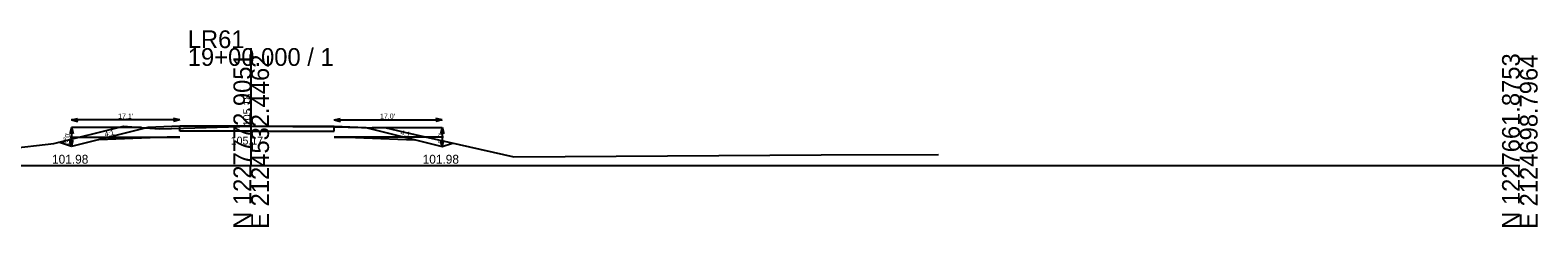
# Model space of a CAD drawing. Extents: x -26 to 1403, y -10 to 9574.
# Drawn here: x 1165.2 to 1402.8, y 8990.3 to 9021.3 of the extents above; entities that cross this region are included whole.
import ezdxf

# ---------------------------------------------------------------- set-up
doc = ezdxf.new("R2010")
doc.units = 0
for name, color, linetype in [('XS_CELL', 7, 'Continuous'), ('XS_P_FINISHED_GRADE', 7, 'Continuous'), ('XS_P_FINISHED_GRADE_ELEV_TX', 7, 'Continuous'), ('XS_P_SUBGRADE_GRANULAR', 7, 'Continuous'), ('XS_P_SUBGRADE_PAVEMENT', 7, 'Continuous'), ('XS_P_TX_CLEARZONE', 7, 'Continuous'), ('XS_P_TX_DCH', 7, 'Continuous'), ('XS_P_TX_FS_BS', 7, 'Continuous'), ('XS_X_GROUND', 7, 'Continuous'), ('XS_X_GROUND_TX', 7, 'Continuous')]:
    doc.layers.add(name, color=color, linetype=linetype)

msp = doc.modelspace()

# ---------------------------------------------------------------- linework, layer by layer
at = {"layer": 'XS_CELL'}
for p, q in [((1200, 9000), (1200, 9018.51)), ((1000, 9000), (1200, 9000)), ((1200, 9000), (1400, 9000))]:
    msp.add_line(p, q, dxfattribs=at)
at = {"layer": 'XS_P_FINISHED_GRADE'}
for p, q in [((1183.73, 9005.98), (1171.67, 9002.98)), ((1188.75, 9006.18), (1183.73, 9005.98)), ((1200, 9006.18), (1188.75, 9006.18)), ((1200, 9006.18), (1213.09, 9006.18)), ((1213.09, 9006.18), (1218.09, 9005.98)), ((1218.09, 9005.98), (1230.1, 9002.98)), ((1171.67, 9002.98), (1169.64, 9003.65)), ((1230.1, 9002.98), (1231.75, 9003.53))]:
    msp.add_line(p, q, dxfattribs=at)
at = {"layer": 'XS_P_SUBGRADE_GRANULAR'}
for p, q in [((1171.47, 9004.48), (1188.75, 9004.48)), ((1186.75, 9004.48), (1175.96, 9004.05)), ((1188.75, 9004.48), (1186.75, 9004.48)), ((1230.3, 9004.48), (1213.09, 9004.48)), ((1213.09, 9004.48), (1215.09, 9004.48)), ((1215.09, 9004.48), (1225.81, 9004.05))]:
    msp.add_line(p, q, dxfattribs=at)
at = {"layer": 'XS_P_SUBGRADE_PAVEMENT'}
for p, q in [((1188.75, 9005.43), (1188.75, 9006.18)), ((1213.09, 9005.43), (1213.09, 9006.18)), ((1200, 9005.43), (1188.75, 9005.43)), ((1200, 9005.43), (1213.09, 9005.43))]:
    msp.add_line(p, q, dxfattribs=at)
at = {"layer": 'XS_P_TX_CLEARZONE'}
for p, q in [((1171.67, 9005.98), (1171.42, 9004.98)), ((1171.67, 9007.18), (1172.67, 9007.43)), ((1171.67, 9007.18), (1172.67, 9006.93)), ((1188.75, 9007.18), (1171.67, 9007.18)), ((1171.67, 9005.98), (1171.92, 9004.98)), ((1171.67, 9005.98), (1171.67, 9002.98)), ((1182.72, 9005.98), (1171.67, 9005.98)), ((1188.75, 9007.18), (1187.75, 9007.43)), ((1188.75, 9007.18), (1187.75, 9006.93)), ((1213.09, 9007.18), (1214.09, 9007.43)), ((1213.09, 9007.18), (1214.09, 9006.93)), ((1213.09, 9007.18), (1230.1, 9007.18)), ((1219.09, 9005.98), (1230.1, 9005.98)), ((1230.1, 9007.18), (1229.09, 9007.43)), ((1230.1, 9007.18), (1229.09, 9006.93)), ((1230.1, 9005.98), (1229.85, 9004.98)), ((1230.1, 9005.98), (1230.1, 9002.98)), ((1230.1, 9005.98), (1230.35, 9004.98)), ((1171.67, 9002.98), (1171.42, 9003.98)), ((1171.67, 9002.98), (1171.92, 9003.98)), ((1230.1, 9002.98), (1229.85, 9003.98)), ((1230.1, 9002.98), (1230.35, 9003.98))]:
    msp.add_line(p, q, dxfattribs=at)
at = {"layer": 'XS_X_GROUND'}
for p, q in [((1168.86, 9003.46), (1179.86, 9006.17)), ((1179.86, 9006.17), (1182.49, 9006)), ((1182.49, 9006), (1185.53, 9005.79)), ((1189.35, 9005.9), (1200.02, 9006.17)), ((1200.02, 9006.17), (1213.12, 9006.07)), ((1213.12, 9006.07), (1219.52, 9005.94)), ((1219.52, 9005.94), (1221.05, 9005.99)), ((1221.05, 9005.99), (1224.15, 9005.24)), ((1185.53, 9005.79), (1189.35, 9005.9)), ((1224.15, 9005.24), (1241.38, 9001.37)), ((1161.56, 9002.63), (1168.86, 9003.46)), ((1241.38, 9001.37), (1289.85, 9001.68)), ((1289.85, 9001.68), (1308.34, 9001.7))]:
    msp.add_line(p, q, dxfattribs=at)

# ---------------------------------------------------------------- texts
at = {"layer": 'XS_CELL'}
for s, p in [('LR61', (1190, 9018.51)), ('19+00.000 / 1', (1190, 9015.71))]:
    msp.add_text(s, height=2.8, dxfattribs=at).set_placement(p)
for s, p in [('N 1227772.9051', (1200, 8990)), ('E 2124532.4462', (1202.8, 8990)), ('N 1227661.8753', (1400, 8990)), ('E 2124698.7964', (1402.8, 8990))]:
    msp.add_text(s, height=2.8, rotation=90, dxfattribs=at).set_placement(p)
at = {"layer": 'XS_P_FINISHED_GRADE_ELEV_TX'}
msp.add_text('105.18', height=1.25, rotation=90, dxfattribs=at).set_placement((1199.99, 9006.19))
at = {"layer": 'XS_P_TX_CLEARZONE'}
for s, p in [("17.1'", (1179.02, 9007.38)), ("17.0'", (1220.31, 9007.38))]:
    msp.add_text(s, height=0.8, dxfattribs=at).set_placement(p)
for p in [(1171.47, 9003.45), (1230.3, 9003.45)]:
    msp.add_text("3.0'", height=0.8, rotation=90, dxfattribs=at).set_placement(p)
at = {"layer": 'XS_P_TX_DCH'}
for p in [(1168.6, 9000.28), (1227.03, 9000.28)]:
    msp.add_text('101.98', height=1.4, dxfattribs=at).set_placement(p)
at = {"layer": 'XS_P_TX_FS_BS'}
for s, rotation, p in [('3:1', 341.6494, (1170.07, 9003.72)), ('4:1', 13.9701, (1176.99, 9004.51)), ('4:1', 345.9674, (1223.48, 9004.84))]:
    msp.add_text(s, height=0.8, rotation=rotation, dxfattribs=at).set_placement(p)
at = {"layer": 'XS_X_GROUND_TX'}
msp.add_text('105.17', height=1.25, rotation=360, dxfattribs=at).set_placement((1196.77, 9003.29))

doc.saveas('drawing.dxf')
